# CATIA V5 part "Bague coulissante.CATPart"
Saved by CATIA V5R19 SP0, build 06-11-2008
Part number: Bague coulissante
Bounding box of the stored display mesh (mm): x -20 to 20, y -20 to 20, z 1.42 to 25
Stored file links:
  C:\Users\Laurent\Desktop\Sujet National E33\CFAO Catia\Bague coulissante.CATPart
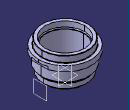
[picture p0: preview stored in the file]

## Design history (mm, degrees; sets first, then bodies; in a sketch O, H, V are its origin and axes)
Body1 (main body)
  Sketch1 on xy-plane, origin (0, 0, 0), H (1, 0, 0), V (0, 1, 0)
    circle A1 centre (0, 0) radius 22.5
    radius A1 = 22.5
  Pad1: profile Sketch1, direction (0, 0, 1), length 25
  Sketch2 on end face of Pad1, origin (0, 0, 25), H (1, 0, 0), V (0, 1, 0)
    circle A1 centre (0, 0) radius 17.45
    radius A1 = 17.45
  Pocket1: profile Sketch2, direction (0, 0, -1), length 4.78, outer side
  Sketch3 on end face of Pad1, origin (0, 0, 25), H (1, 0, 0), V (0, 1, 0)
    circle A1 centre (0, 0) radius 20
    radius A1 = 20
  Pocket2: profile Sketch3, direction (0, 0, -1), length 10, outer side
  Sketch4 on end face of Pad1, origin (0, 0, 25), H (1, 0, 0), V (0, 1, 0)
    circle A1 centre (0, 0) radius 10
    radius A1 = 10
  Pocket3: profile Sketch4, direction (0, 0, -1), through (limit type 3)
  Sketch5 on end face of Pad1, origin (0, 0, 25), H (1, 0, 0), V (0, 1, 0)
    circle A1 centre (0, 0) radius 14.95
    radius A1 = 14.95
  Pocket4: profile Sketch5, direction (0, 0, -1), length 4.78
  Sketch6 on zx-plane, origin (0, 0, 0), H (-1, 0, 0), V (0, 0, 1)
    axis line L1 (-25.6583, 20.6) -> (32.7674, 20.6)
    arc A1 centre (14.79, 20.6) radius 0.5 from (14.79, 20.1) to (14.79, 21.1) ccw
    point P3 (14.79, 20.6)
    reference projected line E1 (-17.45, 25) -> (17.45, 25) from edge [face of Pocket1 from Sketch2.A1 | end face of Pad1]
    line L2 (14.79, 20.1) -> (0, 20.1)
    point P4 (0, 20.1)
    line L3 (14.79, 21.1) -> (0, 21.1)
    point P5 (0, 21.1)
    line L4 (0, 20.1) -> (0, 21.1)
    reference projected line E2 through (0, 0) direction (0, 1) from axis of face of Pocket1 from Sketch2.A1
    distance L1 E1 = 4.4
    radius A1 = 0.5
    distance A1 E2 = 15.29
    horizontal: L1 H, L2 H, L3 H
    coincidence: P3 L1, P4 V, P5 V
    tangency: L3 A1, L2 A1
    vertical: L4 V
  Groove1: profile Sketch6, axis axis of face of Pocket2 from Sketch3.A1, angle 360
  Fillet1: radius 0.3, on edge [face of Pocket1 from Sketch2.A1 | end face of Pad1]; edge [end face of Pocket1 | face of Pocket1 from Sketch2.A1]
  Sketch7 on start face of Pad1, origin (0, 0, 0), H (1, 0, 0), V (0, -1, 0)
    circle A1 centre (0, 0) radius 23.7695
  Pocket5: profile Sketch7, direction (0, 0, 1), length 1.42
  Sketch8 on end face of Pocket5, origin (0, 0, 1.42), H (1, 0, 0), V (0, -1, 0)
    circle A1 centre (0, 0) radius 17.9915
    radius A1 = 17.9915
  Pocket6: profile Sketch8, direction (0, 0, 1), length 14.8, outer side
  Sketch9 on end face of Pocket5, origin (0, 0, 1.42), H (1, 0, 0), V (0, -1, 0)
    circle A1 centre (0, 0) radius 16.5
    radius A1 = 16.5
  Pocket7: profile Sketch9, direction (0, 0, 1), length 6.8, outer side
  Chamfer1: length 1.5, angle 45, on edge [face of Pocket7 from Sketch9.A1 | end face of Pocket5]
  Sketch10 on zx-plane, origin (0, 0, 0), H (-1, 0, 0), V (0, 0, 1)
    line L1 (15.5, 8.22) -> (15.5, 6.22)
    line L2 (15.5, 6.22) -> (31.9529, 6.22)
    line L3 (15.5, 8.22) -> (31.9529, 8.22)
    line L4 (31.9529, 8.22) -> (31.9529, 6.22)
    reference projected line E1 (14.5, 1.42) -> (-14.5, 1.42) from edge [face of Chamfer1 | end face of Pocket5]
    reference projected line E2 through (0, 0) direction (0, -1) from axis of face of Pocket7 from Sketch9.A1
    distance L3 E1 = 6.8
    distance L1 E2 = 15.5
    distance L3 L2 = 2
    vertical: L1 V, L4 V
    horizontal: L2 H, L3 H
  Groove2: profile Sketch10, axis axis of face of Chamfer1, angle 360
  Fillet2: radius 0.5, on edge [face of Groove2 from Sketch10.L1 | face of Groove2]; edge [face of Groove2 from Sketch10.L2 | face of Groove2 from Sketch10.L1]
  Sketch11 on end face of Pocket5, origin (0, 0, 1.42), H (1, 0, 0), V (0, -1, 0)
    circle A1 centre (0, 0) radius 14.2912
    radius A1 = 14.2912
  Pocket8: profile Sketch11, direction (0, 0, -1), through (limit type 3)
  Chamfer2: length 0.9, angle 30, on edge [end face of Pocket5 | face of Pocket8 from Sketch11.A1]
  Plane1: type Offset, Offset 19, RefPlane yz-plane
  Sketch12 on Plane1, origin (19, 0, 0), H (0, 1, 0), V (0, 0, 1)
    line L1 (-10, 18.22) -> (10, 18.22)
    line L2 (10, 18.22) -> (10, 14.8867)
    line L3 (10, 14.8867) -> (-10, 14.8867)
    line L4 (-10, 14.8867) -> (-10, 18.22)
    reference projected line E1 (20, 16.22) -> (-20, 16.22) from edge [face of Pocket2 from Sketch3.A1 | end face of Pocket6]
    reference projected line E2 through (0, 0) direction (0, -1) from axis of face of Pocket6 from Sketch8.A1
    reference projected line E3 through (0, 0) direction (0, -1) from axis of face of Pocket6 from Sketch8.A1
    distance L1 E1 = 2
    distance L2 E2 = 10
    distance L4 E3 = 10
    horizontal: L1 H, L3 H
    vertical: L2 V, L4 V
  Pocket9: profile Sketch12, direction (1, 0, 0), through (limit type 3)
  Mirror1: of Pocket9, about yz-plane
  Thread1: diameter 33, depth 4.8, pitch 1.5, on face of Pocket7 from Sketch9.A1, from end face of Pocket5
